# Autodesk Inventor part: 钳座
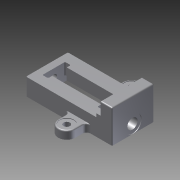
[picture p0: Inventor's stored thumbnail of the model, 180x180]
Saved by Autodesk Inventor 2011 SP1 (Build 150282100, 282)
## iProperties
Created: 2013-11
Part Number: 钳座
Document SubType Name: Modeling
Designer: user
Density: 1 g/cm^3
Author: user
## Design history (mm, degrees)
sketch "草图1"
  geometry: L1 (-124, 37)-(0, 37); L2 (0, 37)-(0, -37); L3 (0, -37)-(-124, -37); L4 (-124, -37)-(-124, 37); 2 further points
  constraints: 8 end point, 2 parallel, 1 coincident, 1 horizontal, 1 midpoint, 1 perpendicular
  dimensions: "d0" = 124 distance of L1.start L1.end; "d1" = 74 distance of L1.end L2.end
extrude "拉伸1" new body sketch "草图1" distance "d2" = 30; taper "d3" = 0 deg
sketch "草图2"
  geometry: L1 (124, 0)-(124, 30) reference; L2 (124, 0)-(152, 0); L3 (152, 0)-(152, 58); L4 (152, 58)-(132, 58); L5 (132, 58)-(132, 36); L6 (132, 36)-(124, 36); L7 (124, 36)-(124, 0)
  constraints: 12 end point, 3 parallel, 2 perpendicular
  dimensions: "d4" = 28 distance of L1.start L2.end; "d5" = 58 distance of L2.end L3.end; "d6" = 20 distance of L3.end L4.end; "d7" = 22 distance of L4.end L5.end; "d8" = 8 distance of L5.end L6.end
extrude "拉伸2" join sketch "草图2" distance "d9" = 74; taper "d10" = 0 deg
sketch "草图3"
  geometry: L1 (0, 37)-(0, -37) reference; L2 (0, -37)-(-124, -37) reference; L3 (-112, 0)-(-112, 20); L4 (-112, 20)-(-102, 20); L5 (-102, 20)-(-102, 13); L6 (-102, 13)-(-15, 13); L7 (-15, 13)-(-15, 20); L8 (-15, 20)-(0, 20); L9 (0, 20)-(0, 0); L10 (0, -37)-(0, 37); L11 (0, -20)-(0, 0); L12 (-15, -20)-(0, -20); L13 (-15, -13)-(-15, -20); L14 (-102, -13)-(-15, -13); L15 (-102, -20)-(-102, -13); L16 (-112, -20)-(-102, -20); L17 (-112, 0)-(-112, -20); L18 (0, 20)-(0, -20); L19 (0, -20)-(0, 20); 1 further point
  constraints: 34 end point, 4 collinear, 3 parallel, 2 perpendicular, 1 midpoint
  dimensions: "d11" = 20 distance of L3.start L3.end; "d12" = 10 distance of L3.end L4.end; "d13" = 7 distance of L4.end L5.end; "d14" = 87 distance of L5.end L6.end; "d15" = 7 distance of L6.end L7.end; "d16" = 15 distance of L7.end L8.end
extrude "拉伸3" cut sketch "草图3" distance "d17" = 20; taper "d18" = 0 deg
sketch "草图4"
  geometry: L1 (0, -37)-(0, 37) reference; L2 (112, -23)-(0, -23); L3 (0, -23)-(0, 23); L4 (0, 23)-(112, 23); L5 (112, 23)-(112, -23); 2 further points
  constraints: 8 end point, 2 midpoint, 2 parallel, 1 horizontal, 1 perpendicular
  dimensions: "d19" = 46 distance of L2.end L3.end; "d20" = 112 distance of L2.start L2.end
extrude "拉伸4" cut sketch "草图4" distance "d21" = 10; taper "d22" = 0 deg
hole "Hole1" diameter "d25" = 8.376; stored, may be unused: countersink angle "d29" = 90 deg, drill point angle "d31" = 120 deg; dims "d23" = 11, "d24" = 17, "d26" = 14, "d27" = 4, "d28" = 2, "d30" = 16
mirror "镜像1"
hole "Hole2" diameter "d34" = 18; stored, may be unused: countersink angle "d38" = 90 deg, drill point angle "d40" = 0 deg; dims "d32" = 37, "d33" = 15, "d35" = 14, "d36" = 30, "d37" = 1, "d39" = 28
hole "Hole3" diameter "d43" = 12; stored, may be unused: countersink angle "d47" = 90 deg, drill point angle "d49" = 0 deg; dims "d41" = 15, "d42" = 37, "d44" = 14, "d45" = 25, "d46" = 1, "d48" = 28
sketch "草图5"
  geometry: L1 (-28, -37)-(-28, 0) reference; L2 (-28, -37)-(124, -37) reference; L3 (47, -57)-(47, -37); L4 (17, -57)-(17, -37); L5 (124, -37)-(124, 37) reference; L6 (139.884, 0)-(-39.981, 0); L7 (47, 57)-(47, 37); L8 (17, 57)-(17, 37); A1 r 15 centre (32, -57) between (17, -57) and (47, -57); A2 r 15 centre (32, 57) between (47, 57) and (17, 57); 1 further point
  constraints: 10 end point, 5 symmetric about line, 4 point on circle, 3 perpendicular, 2 centre point, 2 point on line, 2 tangent, 1 other
  dimensions: "d50" = 30 diameter of A1; "d51" = 45 distance between parallel lines of L1 L4; "d63" = 20 distance of L3.start L3.end
extrude "拉伸5" join sketch "草图5" distance "d52" = 14; taper "d53" = 0 deg
hole "Hole4" diameter "d56" = 11; stored, may be unused: countersink angle "d60" = 90 deg, drill point angle "d62" = 0 deg; dims "d54" = 10, "d55" = 10, "d57" = 14, "d58" = 25, "d59" = 1, "d61" = 28
fillet "圆角1" dims "d64" = 7
fillet "圆角2" dims "d65" = 2
fillet "圆角3" dims "d66" = 2
fillet "圆角4" dims "d67" = 2
sketch "草图6"
  geometry: L1 (122, 37)-(-26, 37) reference; L2 (17, 57)-(17, 37); L3 (47, 57)-(47, 37); A1 r 15 centre (32, 57) between (47, 57) and (17, 57); 1 further point
  constraints: 4 end point, 2 perpendicular, 2 point on circle, 2 point on line, 2 tangent, 1 centre point
  dimensions: "d68" = 30 diameter of A1; "d69" = 20 distance of L2.start L2.end
extrude "拉伸6" join sketch "草图6" distance "d70" = 14; taper "d71" = 0 deg
fillet "圆角6" dims "d82" = 7
fillet "圆角7" dims "d83" = 2
hole "Hole6" diameter "d86" = 11; stored, may be unused: countersink angle "d90" = 90 deg, drill point angle "d92" = 0 deg; dims "d84" = 10, "d85" = 10, "d87" = 6, "d88" = 25, "d89" = 1, "d91" = 8
fillet "圆角8" dims "d93" = 2
node "实体1"
